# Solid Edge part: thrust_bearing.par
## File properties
Title: Thrust bearing
Author: Abhinav Rai
Template: Normal.par
Last saved by: CADCIM
Revision: 13
Application: Solid Edge
Accuracy: 0.99
Material: aluminum
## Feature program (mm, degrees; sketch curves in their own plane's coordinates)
sketch for "unnamed RevolvedProtrusion 1" plane through (0, 0, 0) normal (0, -1, 0) x-axis (1, 0, 0)
  line (47.625, 16.8036) -> (66.929, 16.8036)
  line (66.929, 16.8036) -> (73.025, 10.7076)
  line (73.025, 10.7076) -> (73.025, -12.0254)
  line (73.025, -12.0254) -> (66.929, -18.1214)
  line (66.929, -18.1214) -> (47.625, -18.1214)
  line (47.625, -18.1214) -> (47.625, -7.1994)
  line (61.5714, -7.1994) -> (47.625, -7.1994)
  line (61.5714, 5.8816) -> (61.5714, -7.1994)
  line (47.625, 5.8816) -> (61.5714, 5.8816)
  line (47.625, 5.8816) -> (47.625, 16.8036)
revolve "unnamed RevolvedProtrusion 1" add finite 360 deg
sketch for "unnamed RevolvedProtrusion 2" plane through (0, 0, 0) normal (1, 0, 0) x-axis (0, 1, 0)
  line (69.977, 13.7556) -> (73.0652, 13.7556)
  line (73.0652, 13.7556) -> (74.6125, 12.2083)
  line (74.6125, 12.2083) -> (74.6125, -13.4669)
  line (74.6125, -13.4669) -> (73.006, -15.0734)
  line (73.006, -15.0734) -> (69.977, -15.0734)
revolve "unnamed RevolvedProtrusion 2" add full turn 360 deg
sketch for "unnamed RevolvedProtrusion 3" plane through (0, 0, 0) normal (0, -1, 0) x-axis (1, 0, 0)
revolve "unnamed RevolvedProtrusion 3" add full turn 360 deg about sketch line (-54.9674, 10.1232) -> (-54.9674, -18.1214)
pattern "unnamed Pattern 1" of "unnamed RevolvedProtrusion 3"
pattern "unnamed Pattern 2"
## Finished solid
Body 1: solid body, 39 faces, 39 edges, 25 vertices.
  Faces by surface: torus 25, plane 6, cone 4, cylinder 4
  Edges by curve: circle 39
Bounding box of the edges (mm; curved faces can reach further): 149.225 x 149.225 x 34.925, from (-74.6125, -74.6125, -18.1214) to (74.6125, 74.6125, 16.8036).
Cylindrical faces by radius (mm): R47.625 x2, R61.5714 x1, R74.6125 x1
Conical faces (half-angle, radius in mm at the cone's reference point): 45 deg R66.929 x1, 45 deg R73.025 x1, 45 deg R73.0652 x1, 45 deg R74.6125 x1
Toroidal faces (ring radius, tube radius in mm): R-0.1023 r6.604 x25
Planar faces by outward normal: +z 3, -z 3
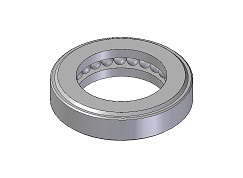
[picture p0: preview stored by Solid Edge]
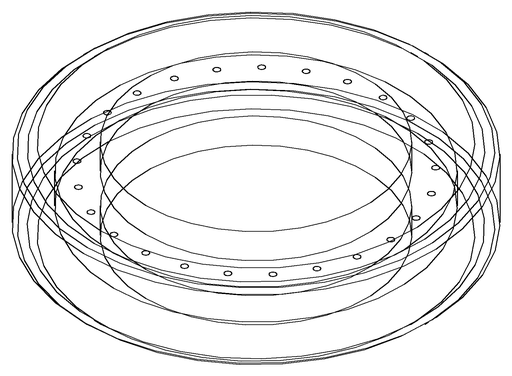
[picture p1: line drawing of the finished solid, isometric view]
